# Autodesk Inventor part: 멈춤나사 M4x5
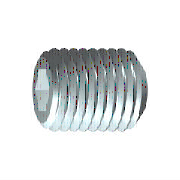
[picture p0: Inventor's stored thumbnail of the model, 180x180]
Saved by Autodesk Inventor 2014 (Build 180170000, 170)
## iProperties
IsCustomPart: 1
Created: 2012-02
Part Number: 멈춤나사 M4x5
Material: 강철, 연강
Description: 6각 소켓 머리 없는 멈춤 나사
Document SubType Name: Modeling
Standard: KS B 1028
Designer: mduedu
Standards Organization: KS
Language: ko-KR
Size Designation: 납작점M4x5
Categories: <MemberInstance><Categories><Category DisplayName="조임쇠" InternalName="e4da775c-781d-43d5-af7c-5136215cf5a6" Mnemonic="FSTN"><Category DisplayName="볼트" InternalN
Density: 1 g/cm^3
Appearance: Steel
Author: mduedu
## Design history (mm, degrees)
sketch "스케치1"
  geometry: L1 (0, 0)-(1.833, 0); L2 (5, 1.155)-(5, 2); L3 (5, 2)-(0, 2); L4 (5, 1.155)-(2.5, 1.155); L5 (2.5, 1.155)-(1.833, 0); L6 (0, -0.4)-(0, 2.4) reference; L7 (0, 2)-(0, 0)
  constraints: 13 end point, 3 parallel, 1 collinear, 1 perpendicular, 1 point on line
  dimensions: "d0" = 2.5 distance of L2.start L4.end (= INTI); "d1" = 60 deg angle of L5 L1; "d2" = 4 diameter of L3 L1 (= NND); "d3" = 2.3094 diameter of L4 L1 (= 1.1547 x SW); "d5" = 5 distance from line of L2 L3.end (= NLG)
revolve "본체" sketch "스케치1" stored, may be unused: angle "d6" = 90 deg
sketch "스케치2"
  geometry: L1 (-0.577, 1)-(0.577, 1); L2 (0.577, 1)-(1.155, 0); L3 (1.155, 0)-(0.577, -1); L4 (0.577, -1)-(-0.577, -1); L5 (-0.577, -1)-(-1.155, 0); L6 (-1.155, 0)-(-0.577, 1); A1 r 1.155 centre (0, 0) between (-0.577, 1) and (0.577, 1) reference; 2 further points
  constraints: 12 end point, 2 point on circle, 1 coincident, 1 horizontal, 11 other
extrude "슬롯" join sketch "스케치2" taper "d9" = 0 deg; stored distance "d21" = 10
workaxis "Work Axis1"
workplane "Work Plane1"
sketch "Sketch4"
  geometry: L1 (-5, -1.155)-(-2.5, -1.155) reference; L2 (-2.5, -1.155)-(-1.833, 0) reference; L3 (-1.833, 0)-(-2.5, 1.155) reference; L4 (-2.5, 1.155)-(-5, 1.155) reference; L5 (-5, 1.155)-(-5, 1.571) reference; L6 (-5, 1.571)-(-4.571, 2) reference; L7 (-4.571, 2)-(-0.429, 2) reference; L8 (-0.429, 2)-(0, 1.571) reference; L9 (0, 1.571)-(0, -1.571) reference; L10 (0, -1.571)-(-0.429, -2) reference; L11 (-0.429, -2)-(-4.571, -2) reference; L12 (-4.571, -2)-(-5, -1.571) reference; L13 (-5, -1.571)-(-5, -1.155) reference; 1 further point
  node "Project Cut Edges1"
body "Solid1"
chamfer "모따기1" distance "d7" = 0.42941 (= -0.5 x GD1 + 0.5 x NND); stored, may be unused: angle "d8" = 45 deg (= FAWI), second distance "d29" = 0.42941 (= -0.5 x GD1 + 0.5 x NND)
feature "스레드" dims "d11" = 5 (= NLG), "d12" = 0
chamfer "모따기2" distance "d13" = 0.42941 (= -0.5 x GD1 + 0.5 x NND); stored, may be unused: angle "d14" = 45 deg (= FAWI), second distance "d30" = 0.42941 (= -0.5 x GD1 + 0.5 x NND)
other parameters: "NND" = 4 [user parameter; used in 5 equation terms], "NLG" = 5 [user parameter; used in 2 equation terms], "INTI" = 2.5 [user parameter; used in 1 equation term], "FAWI" = 45 deg [user parameter; used in 2 equation terms], "SW" = 2 [user parameter; used in 2 equation terms], "GD1" = 3.14117 (= THREADDIA - 1.2269 x PTC) [user parameter; used in 4 equation terms], "d4" = 0, "FAWI1" = 45 deg [user parameter], "d15" = 0, "d31" = 0, "GUL" = 0.42941 (= 0.61345 x PTC) [user parameter], "SPD" = 2.5 [user parameter], "TPU" = 14.28571 (computed from PTC) [user parameter], "TOA" = 30 deg [user parameter], "THREADDIA" = 4 [user parameter; used in 1 equation term], "PTC" = 0.7 [user parameter; used in 4 equation terms], "GAL" = 0.42941 (= 0.61345 x PTC) [user parameter], "E0" = 2.31 (= 1.155 x SW) [user parameter]
